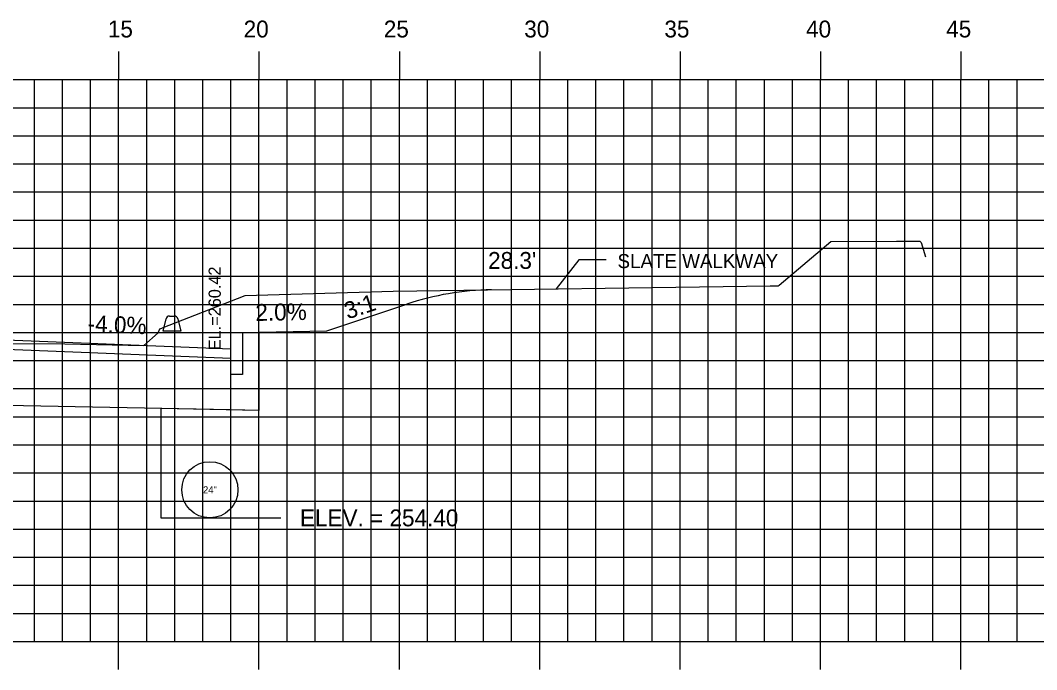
# Model space of a CAD drawing. Extents: x 856235 to 856405, y 366268 to 366378.
# Drawn here: x 856329.28 to 856365.48, y 366323.88 to 366346.99 of the extents above; entities that cross this region are included whole.
import ezdxf

# ---------------------------------------------------------------- set-up
doc = ezdxf.new("R2010")
doc.units = 0
for name, color, linetype in [('ANNOTATION', 7, 'Continuous'), ('D_Curb_Type_1_Rt', 7, 'Continuous'), ('D_Roadway_Edge_Shoulder', 7, 'Continuous'), ('D_Roadway_FinishedGrade', 7, 'Continuous'), ('D_Roadway_SubGrade', 7, 'Continuous'), ('D_Text_Monospaced', 7, 'Continuous'), ('D_Text_Standard', 7, 'Continuous'), ('H_V ANNOTATION', 7, 'Continuous'), ('junk strct exc', 7, 'Continuous'), ('MAJOR', 7, 'Continuous'), ('MINOR', 7, 'Continuous'), ('PDRAIN', 7, 'Continuous'), ('S_Curb_Type_3', 7, 'Continuous'), ('S_Roadway_Centerline', 7, 'Continuous')]:
    doc.layers.add(name, color=color, linetype=linetype)

msp = doc.modelspace()

# ---------------------------------------------------------------- linework, layer by layer
at = {"layer": 'ANNOTATION'}
msp.add_lwpolyline([(856350.152, 366338.465), (856349.177, 366338.465), (856348.367, 366337.436)], dxfattribs=at)
at = {"layer": 'D_Curb_Type_1_Rt'}
msp.add_lwpolyline([(856337.197, 366335.883), (856337.197, 366334.383), (856336.78, 366334.383), (856336.78, 366335.883)], close=True, dxfattribs=at)
at = {"layer": 'D_Roadway_Edge_Shoulder'}
msp.add_lwpolyline([(856317.781, 366335.84), (856328.781, 366335.62), (856336.78, 366335.3)], dxfattribs=at)
at = {"layer": 'D_Roadway_FinishedGrade'}
for points in [[(856340.197, 366335.943), (856343.044, 366336.892)], [(856337.197, 366335.883), (856340.197, 366335.943)]]:
    msp.add_lwpolyline(points, dxfattribs=at)
msp.add_arc((856346.206, 366327.405), 10, 90.8085, 108.4301, dxfattribs=at)
at = {"layer": 'D_Roadway_SubGrade'}
for points in [[(856337.781, 366335.895), (856337.781, 366333.106), (856336.781, 366333.126)], [(856336.781, 366333.126), (856328.781, 366333.286), (856328.781, 366335.286), (856336.781, 366334.966)]]:
    msp.add_lwpolyline(points, dxfattribs=at)
at = {"layer": 'D_Text_Standard'}
msp.add_lwpolyline([(856337.781, 366329.285), (856337.88, 366329.285), (856338.56, 366329.285)], dxfattribs=at)
at = {"layer": 'junk strct exc'}
msp.add_lwpolyline([(856334.281, 366333.176), (856334.281, 366329.285), (856337.781, 366329.285), (856337.781, 366333.106)], close=True, dxfattribs=at)
at = {"layer": 'MAJOR'}
for p, q in [((856332.781, 366345.887), (856332.781, 366344.885)), ((856337.781, 366345.887), (856337.781, 366344.885)), ((856342.781, 366345.887), (856342.781, 366344.885)), ((856347.781, 366345.887), (856347.781, 366344.885)), ((856352.781, 366345.887), (856352.781, 366344.885)), ((856357.781, 366345.887), (856357.781, 366344.885)), ((856362.781, 366345.887), (856362.781, 366344.885)), ((856247.781, 366344.885), (856387.781, 366344.885)), ((856247.781, 366344.885), (856387.781, 366344.885)), ((856332.781, 366324.885), (856332.781, 366344.885)), ((856337.781, 366324.885), (856337.781, 366344.885)), ((856342.781, 366324.885), (856342.781, 366344.885)), ((856347.781, 366324.885), (856347.781, 366344.885)), ((856352.781, 366324.885), (856352.781, 366344.885)), ((856357.781, 366324.885), (856357.781, 366344.885)), ((856362.781, 366324.885), (856362.781, 366344.885)), ((856247.781, 366339.885), (856387.781, 366339.885)), ((856247.781, 366334.885), (856387.781, 366334.885)), ((856247.781, 366329.885), (856387.781, 366329.885)), ((856247.781, 366324.885), (856387.781, 366324.885)), ((856247.781, 366324.885), (856387.781, 366324.885)), ((856332.781, 366323.883), (856332.781, 366324.885)), ((856337.781, 366323.883), (856337.781, 366324.885)), ((856342.781, 366323.883), (856342.781, 366324.885)), ((856347.781, 366323.883), (856347.781, 366324.885)), ((856352.781, 366323.883), (856352.781, 366324.885)), ((856357.781, 366323.883), (856357.781, 366324.885)), ((856362.781, 366323.883), (856362.781, 366324.885))]:
    msp.add_line(p, q, dxfattribs=at)
at = {"layer": 'MINOR'}
for p, q in [((856329.781, 366324.885), (856329.781, 366344.885)), ((856330.781, 366324.885), (856330.781, 366344.885)), ((856331.781, 366324.885), (856331.781, 366344.885)), ((856333.781, 366324.885), (856333.781, 366344.885)), ((856334.781, 366324.885), (856334.781, 366344.885)), ((856335.781, 366324.885), (856335.781, 366344.885)), ((856336.781, 366324.885), (856336.781, 366344.885)), ((856338.781, 366324.885), (856338.781, 366344.885)), ((856339.781, 366324.885), (856339.781, 366344.885)), ((856340.781, 366324.885), (856340.781, 366344.885)), ((856341.781, 366324.885), (856341.781, 366344.885)), ((856343.781, 366324.885), (856343.781, 366344.885)), ((856344.781, 366324.885), (856344.781, 366344.885)), ((856345.781, 366324.885), (856345.781, 366344.885)), ((856346.781, 366324.885), (856346.781, 366344.885)), ((856348.781, 366324.885), (856348.781, 366344.885)), ((856349.781, 366324.885), (856349.781, 366344.885)), ((856350.781, 366324.885), (856350.781, 366344.885)), ((856351.781, 366324.885), (856351.781, 366344.885)), ((856353.781, 366324.885), (856353.781, 366344.885)), ((856354.781, 366324.885), (856354.781, 366344.885)), ((856355.781, 366324.885), (856355.781, 366344.885)), ((856356.781, 366324.885), (856356.781, 366344.885)), ((856358.781, 366324.885), (856358.781, 366344.885)), ((856359.781, 366324.885), (856359.781, 366344.885)), ((856360.781, 366324.885), (856360.781, 366344.885)), ((856361.781, 366324.885), (856361.781, 366344.885)), ((856363.781, 366324.885), (856363.781, 366344.885)), ((856364.781, 366324.885), (856364.781, 366344.885)), ((856247.781, 366343.885), (856387.781, 366343.885)), ((856247.781, 366342.885), (856387.781, 366342.885)), ((856247.781, 366341.885), (856387.781, 366341.885)), ((856247.781, 366340.885), (856387.781, 366340.885)), ((856247.781, 366338.885), (856387.781, 366338.885)), ((856247.781, 366337.885), (856387.781, 366337.885)), ((856247.781, 366336.885), (856387.781, 366336.885)), ((856247.781, 366335.885), (856387.781, 366335.885)), ((856247.781, 366333.885), (856387.781, 366333.885)), ((856247.781, 366332.885), (856387.781, 366332.885)), ((856247.781, 366331.885), (856387.781, 366331.885)), ((856247.781, 366330.885), (856387.781, 366330.885)), ((856247.781, 366328.885), (856387.781, 366328.885)), ((856247.781, 366327.885), (856387.781, 366327.885)), ((856247.781, 366326.885), (856387.781, 366326.885)), ((856247.781, 366325.885), (856387.781, 366325.885))]:
    msp.add_line(p, q, dxfattribs=at)
at = {"layer": 'PDRAIN'}
msp.add_lwpolyline([(856334.281, 366333.176), (856334.281, 366329.285), (856337.781, 366329.285), (856337.781, 366333.106)], dxfattribs=at)
msp.add_circle((856336.031, 366330.285), 1, dxfattribs=at)
at = {"layer": 'S_Curb_Type_3'}
for points in [[(856334.892, 366336.372), (856334.995, 366335.927), (856334.37, 366335.927), (856334.472, 366336.372)], [(856334.594, 366336.469), (856334.77, 366336.469)]]:
    msp.add_lwpolyline(points, dxfattribs=at)
for centre, start, end in [((856334.594, 366336.344), 90, 167.0054), ((856334.77, 366336.344), 12.9946, 90)]:
    msp.add_arc(centre, 0.125, start, end, dxfattribs=at)
at = {"layer": 'S_Roadway_Centerline'}
msp.add_lwpolyline([(856317.781, 366335.852), (856324.494, 366335.567), (856328.856, 366335.491), (856330.87, 366335.48), (856333.679, 366335.424), (856334.19, 366335.873), (856334.251, 366336.012), (856334.324, 366336.04), (856334.37, 366336.058), (856335.499, 366336.497), (856337.291, 366337.198), (856342.56, 366337.355), (856355.985, 366337.544), (856356.051, 366337.541), (856356.28, 366337.545), (856356.313, 366337.567), (856358.146, 366339.119), (856360.492, 366339.129), (856361.321, 366339.133), (856361.368, 366339.089), (856361.518, 366338.578)], dxfattribs=at)

# ---------------------------------------------------------------- texts
at = {"layer": 'ANNOTATION'}
for s, rotation, p in [('3:1', 18.4304, (856340.94, 366336.346)), ('2.0%', 1.146, (856337.658, 366336.293)), ('-4.0%', 357.7094, (856331.668, 366335.905))]:
    msp.add_text(s, height=0.6, rotation=rotation, dxfattribs=at).set_placement(p)
at = {"layer": 'D_Text_Monospaced'}
msp.add_text('SLATE WALKWAY', height=0.49998, dxfattribs=at).set_placement((856350.552, 366338.175))
at = {"layer": 'D_Text_Standard'}
for s, p in [("28.3'", (856345.942, 366338.148)), ('ELEV. = 254.40', (856339.24, 366328.985))]:
    msp.add_text(s, height=0.6, dxfattribs=at).set_placement(p)
msp.add_text(' EL.=260.42', height=0.4335, rotation=90, dxfattribs=at).set_placement((856336.42, 366335.089))
at = {"layer": 'H_V ANNOTATION'}
for s, p in [('15', (856332.398, 366346.385)), ('20', (856337.235, 366346.385)), ('25', (856342.227, 366346.385)), ('30', (856347.229, 366346.385)), ('35', (856352.221, 366346.385)), ('40', (856357.267, 366346.385)), ('45', (856362.259, 366346.385))]:
    msp.add_text(s, height=0.6, dxfattribs=at).set_placement(p)
at = {"layer": 'PDRAIN'}
msp.add_text('24"', height=0.25, dxfattribs=at).set_placement((856335.789, 366330.16))

doc.saveas('drawing.dxf')
